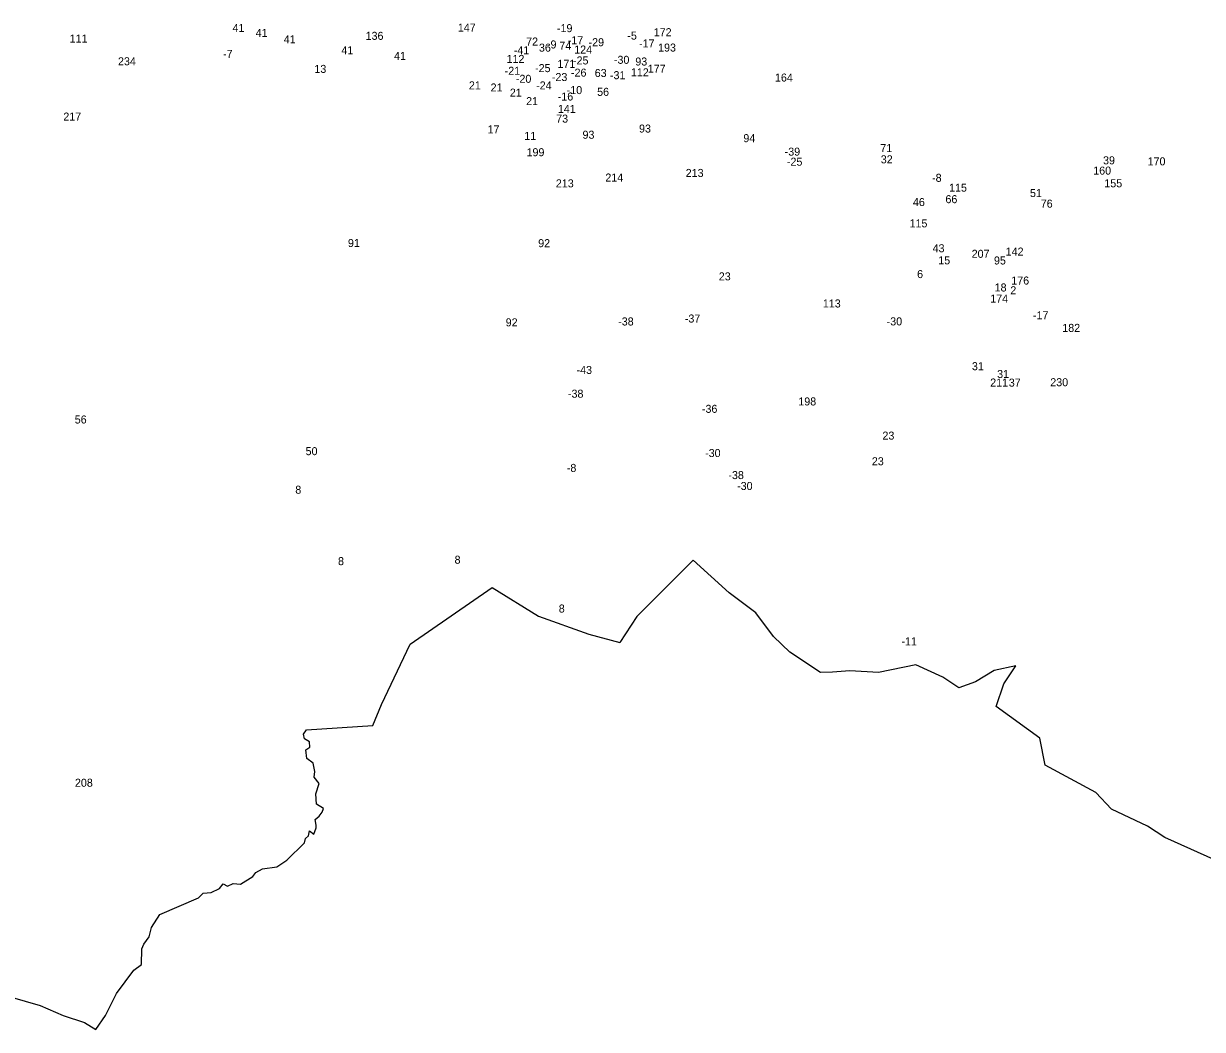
# Model space of a CAD drawing. Extents: x -788870 to -783053, y -967261 to -964403.
# Drawn here: x -787389 to -785917, y -966851 to -965596 of the extents above; entities that cross this region are included whole.
import ezdxf

# ---------------------------------------------------------------- set-up
doc = ezdxf.new("R2010")
doc.units = 0
doc.layers.add('Vrstva 13', color=7, linetype='Continuous')
doc.layers.add('Vrstva 15', color=7, linetype='Continuous')

msp = doc.modelspace()

# ---------------------------------------------------------------- linework, layer by layer
at = {"layer": 'Vrstva 13'}
for p, q in [((-786552.53, -966265.23), (-786623.07, -966335.65)), ((-786507.92, -966306.38), (-786552.53, -966265.23)), ((-786906.25, -966370.25), (-786803.6, -966299.41)), ((-786803.6, -966299.41), (-786745.72, -966335.38)), ((-786474.47, -966331.16), (-786507.92, -966306.38)), ((-786452.45, -966360.57), (-786474.47, -966331.16)), ((-786745.72, -966335.38), (-786683.15, -966357.87)), ((-786623.07, -966335.65), (-786644.2, -966368.18)), ((-786683.15, -966357.87), (-786644.2, -966368.18)), ((-786431.89, -966380.28), (-786452.45, -966360.57)), ((-786942.22, -966445.44), (-786906.25, -966370.25)), ((-786393.65, -966405.49), (-786431.89, -966380.28)), ((-786357.15, -966403.46), (-786378.87, -966405.2)), ((-786321.23, -966405.78), (-786357.15, -966403.46)), ((-786274.6, -966396.22), (-786321.23, -966405.78)), ((-786240.99, -966411.28), (-786274.6, -966396.22)), ((-786176.97, -966403.17), (-786200.15, -966417.37)), ((-786149.74, -966397.37), (-786176.97, -966403.17)), ((-786164.81, -966419.98), (-786149.74, -966397.37)), ((-786378.87, -966405.2), (-786393.65, -966405.49)), ((-786220.72, -966424.9), (-786240.99, -966411.28)), ((-786200.15, -966417.37), (-786220.72, -966424.9)), ((-786174.08, -966448.09), (-786164.81, -966419.98)), ((-786952.9, -966471.96), (-786942.22, -966445.44)), ((-786119.91, -966487.5), (-786174.08, -966448.09)), ((-787039.35, -966482.75), (-787035.79, -966477.41)), ((-787035.79, -966477.41), (-786952.9, -966471.96)), ((-787038.32, -966488.56), (-787039.35, -966482.75)), ((-787031.95, -966492.02), (-787038.32, -966488.56)), ((-787031.58, -966498.95), (-787031.95, -966492.02)), ((-786113.24, -966521.11), (-786119.91, -966487.5)), ((-787036.45, -966502.05), (-787031.58, -966498.95)), ((-787035.14, -966512.92), (-787036.45, -966502.05)), ((-787027.55, -966518.73), (-787035.14, -966512.92)), ((-787025.3, -966529.31), (-787027.55, -966518.73)), ((-786049.81, -966555.59), (-786113.24, -966521.11)), ((-787025.96, -966536.43), (-787025.3, -966529.31)), ((-787019.97, -966544.4), (-787025.96, -966536.43)), ((-787024, -966556.96), (-787019.97, -966544.4)), ((-787023.34, -966570.08), (-787024, -966556.96)), ((-786030.4, -966576.16), (-786049.81, -966555.59)), ((-787014.54, -966575.23), (-787023.34, -966570.08)), ((-787019.78, -966585.16), (-787016.32, -966579.92)), ((-787016.32, -966579.92), (-787014.54, -966575.23)), ((-785985.21, -966597.61), (-786030.4, -966576.16)), ((-787025.03, -966589), (-787019.78, -966585.16)), ((-787023.43, -966596.03), (-787025.03, -966589)), ((-787023.54, -966599.73), (-787023.43, -966596.03)), ((-787036.84, -966612.84), (-787033.09, -966609.47)), ((-787033.09, -966609.47), (-787031.78, -966603.1)), ((-787031.78, -966603.1), (-787026.35, -966607.6)), ((-787026.35, -966607.6), (-787023.54, -966599.73)), ((-785963.49, -966611.52), (-785985.21, -966597.61)), ((-787060.44, -966640.02), (-787038.15, -966618.09)), ((-787038.15, -966618.09), (-787036.84, -966612.84)), ((-785890.49, -966644.57), (-785963.49, -966611.52)), ((-787072.8, -966648.08), (-787060.44, -966640.02)), ((-787099.03, -966655.2), (-787090.6, -966650.52)), ((-787090.6, -966650.52), (-787072.8, -966648.08)), ((-787144.36, -966675.25), (-787139.87, -966669.63)), ((-787139.87, -966669.63), (-787134.25, -966672.44)), ((-787134.25, -966672.44), (-787127.32, -966668.88)), ((-787127.32, -966668.88), (-787118.14, -966669.82)), ((-787118.14, -966669.82), (-787102.59, -966660.26)), ((-787102.59, -966660.26), (-787099.03, -966655.2)), ((-787170.78, -966687.06), (-787164.78, -966681.25)), ((-787164.78, -966681.25), (-787154.67, -966680.31)), ((-787154.67, -966680.31), (-787144.36, -966675.25)), ((-787218.92, -966707.86), (-787170.78, -966687.06)), ((-787229.41, -966724.08), (-787218.92, -966707.86)), ((-787232.04, -966735.69), (-787229.41, -966724.08)), ((-787238.78, -966744.69), (-787232.04, -966735.69)), ((-787241.78, -966770.18), (-787241.4, -966750.69)), ((-787241.4, -966750.69), (-787238.78, -966744.69)), ((-787251.52, -966777.3), (-787241.78, -966770.18)), ((-787272.87, -966806.16), (-787251.52, -966777.3)), ((-787439.92, -966800.94), (-787368.18, -966821.32)), ((-787286.73, -966833.89), (-787272.87, -966806.16)), ((-787368.18, -966821.32), (-787339.76, -966833.96)), ((-787339.76, -966833.96), (-787312.78, -966842.57)), ((-787312.78, -966842.57), (-787299, -966851.18)), ((-787299, -966851.18), (-787286.73, -966833.89))]:
    msp.add_line(p, q, dxfattribs=at)

# ---------------------------------------------------------------- texts
at = {"layer": 'Vrstva 15'}
for s, p in [('111', (-787331.54, -965619.18)), ('41', (-787128.096, -965605.95)), ('41', (-787099.176, -965612.13)), ('136', (-786961.854, -965615.85)), ('147', (-786846.666, -965605.56)), ('-19', (-786722.858, -965606.24)), ('-5', (-786634.93, -965615.57)), ('172', (-786601.98, -965611.3)), ('41', (-787064.076, -965620.08)), ('41', (-786992.096, -965633.77)), ('-41', (-786776.82, -965633.9)), ('72', (-786761.345, -965622.96)), ('36', (-786745.38, -965630.57)), ('-9', (-786735.364, -965626.59)), ('74', (-786719.901, -965628.15)), ('-17', (-786709.374, -965621.35)), ('124', (-786701.287, -965632.95)), ('-29', (-786683.364, -965623.84)), ('-17', (-786620.354, -965625.33)), ('193', (-786596.534, -965630.48)), ('234', (-787271.152, -965647.61)), ('-7', (-787139.909, -965638.42)), ('41', (-786926.306, -965640.84)), ('112', (-786785.826, -965644.67)), ('-25', (-786702.85, -965646.54)), ('-30', (-786651.73, -965645.75)), ('93', (-786625, -965647.89)), ('13', (-787025.851, -965657.13)), ('-21', (-786788.164, -965659.52)), ('-25', (-786750.21, -965656.15)), ('171', (-786722.234, -965650.8)), ('-26', (-786705.344, -965661.79)), ('63', (-786675.71, -965662.21)), ('112', (-786630.536, -965661.44)), ('177', (-786609.408, -965656.81)), ('21', (-786832.871, -965677.68)), ('-20', (-786774.17, -965669.46)), ('-24', (-786748.896, -965677.79)), ('-23', (-786729.23, -965667.31)), ('-31', (-786656.664, -965664.97)), ('164', (-786450.54, -965667.93)), ('21', (-786805.741, -965680.33)), ('21', (-786781.701, -965686.73)), ('-16', (-786721.888, -965691.6)), ('-10', (-786710.715, -965683.57)), ('56', (-786672.68, -965685.75)), ('21', (-786761.401, -965697.32)), ('141', (-786721.731, -965706.99)), ('217', (-787339.41, -965716.61)), ('73', (-786723.845, -965719.17)), ('17', (-786809.56, -965732.61)), ('93', (-786620.36, -965731.58)), ('11', (-786763.636, -965740.73)), ('93', (-786690.95, -965739.31)), ('94', (-786490.036, -965743.59)), ('199', (-786760.838, -965761.14)), ('-39', (-786438.434, -965760.41)), ('71', (-786319.03, -965756.02)), ('-25', (-786435.64, -965772.99)), ('32', (-786318.426, -965770)), ('39', (-786040.77, -965771.25)), ('170', (-785985.12, -965772.56)), ('214', (-786662.417, -965792.74)), ('213', (-786562.041, -965787)), ('-8', (-786254.33, -965793.09)), ('160', (-786053.034, -965784.09)), ('213', (-786724.241, -965800.03)), ('115', (-786233.086, -965805.37)), ('155', (-786039.161, -965799.92)), ('46', (-786278.266, -965823.37)), ('66', (-786237.634, -965819.76)), ('51', (-786132.041, -965812.09)), ('76', (-786118.588, -965825.32)), ('115', (-786282.486, -965849.95)), ('91', (-786983.934, -965874.5)), ('92', (-786746.31, -965874.68)), ('43', (-786253.662, -965881.02)), ('15', (-786246.611, -965896.11)), ('207', (-786204.895, -965887.95)), ('95', (-786177.03, -965896.28)), ('142', (-786162.406, -965885.18)), ('6', (-786273.02, -965913.28)), ('23', (-786520.736, -965916.14)), ('176', (-786155.403, -965921.33)), ('18', (-786176.181, -965929.99)), ('2', (-786156.636, -965933.47)), ('113', (-786390.776, -965949.95)), ('174', (-786181.696, -965943.9)), ('-38', (-786646.4, -965972.41)), ('-37', (-786563.149, -965968.74)), ('-30', (-786311.05, -965972.32)), ('-17', (-786128.354, -965964.68)), ('92', (-786786.89, -965973.53)), ('182', (-786091.681, -965980.44)), ('31', (-786204.551, -966028.26)), ('-43', (-786698.376, -966032.93)), ('31', (-786173.091, -966037.98)), ('211', (-786181.696, -966048.64)), ('37', (-786158.506, -966048.75)), ('230', (-786106.696, -966048.27)), ('-38', (-786709.12, -966062.6)), ('198', (-786421.394, -966072.25)), ('-36', (-786541.804, -966081.47)), ('56', (-787325.17, -966094.79)), ('23', (-786316.296, -966114.9)), ('50', (-787036.796, -966134.33)), ('-30', (-786537.81, -966136.69)), ('23', (-786329.546, -966146.92)), ('-8', (-786710.56, -966155.22)), ('-38', (-786508.72, -966164.18)), ('-30', (-786497.85, -966177.76)), ('8', (-787049.696, -966182.48)), ('8', (-786996.316, -966271.63)), ('8', (-786850.746, -966269.86)), ('8', (-786720.606, -966330.76)), ('-11', (-786292.589, -966371.77)), ('208', (-787324.916, -966548.25))]:
    msp.add_text(s, height=10, dxfattribs=at).set_placement(p)

doc.saveas('drawing.dxf')
